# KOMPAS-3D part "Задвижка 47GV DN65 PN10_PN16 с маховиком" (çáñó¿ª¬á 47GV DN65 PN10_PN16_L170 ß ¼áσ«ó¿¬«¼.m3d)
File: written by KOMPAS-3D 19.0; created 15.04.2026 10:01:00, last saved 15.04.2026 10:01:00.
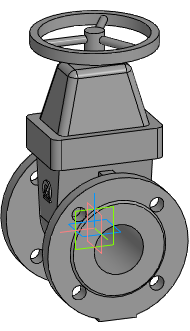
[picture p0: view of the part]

Document properties: Автор: Евгений; Полное имя файла: Z:\3.Личные\kachalov\3d для проектировщиков\2.1 Тип 47GV, 47GV.Z\Задвижка 47GV_DN40-DN600\stp_Задвижка 47GV\Задвижка 47GV DN65 PN10_PN16_L170 с маховиком.m3d

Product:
- Part/product: Задвижка 47GV DN65 PN10_PN16 с маховиком

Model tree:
1. Операция без истории:1  (labels: Задвижка 47GV DN65 PN10_PN16 с маховиком)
